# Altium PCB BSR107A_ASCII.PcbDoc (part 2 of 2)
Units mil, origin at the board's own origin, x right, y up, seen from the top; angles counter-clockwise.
Board outline 2500 x 2500 mil, 4 copper layers (Top Layer, Signal Layer 1, Signal Layer 2, Bottom Layer), stack 64.4 mil thick; 58 components, 15 nets, 89 pads, 265 vias.
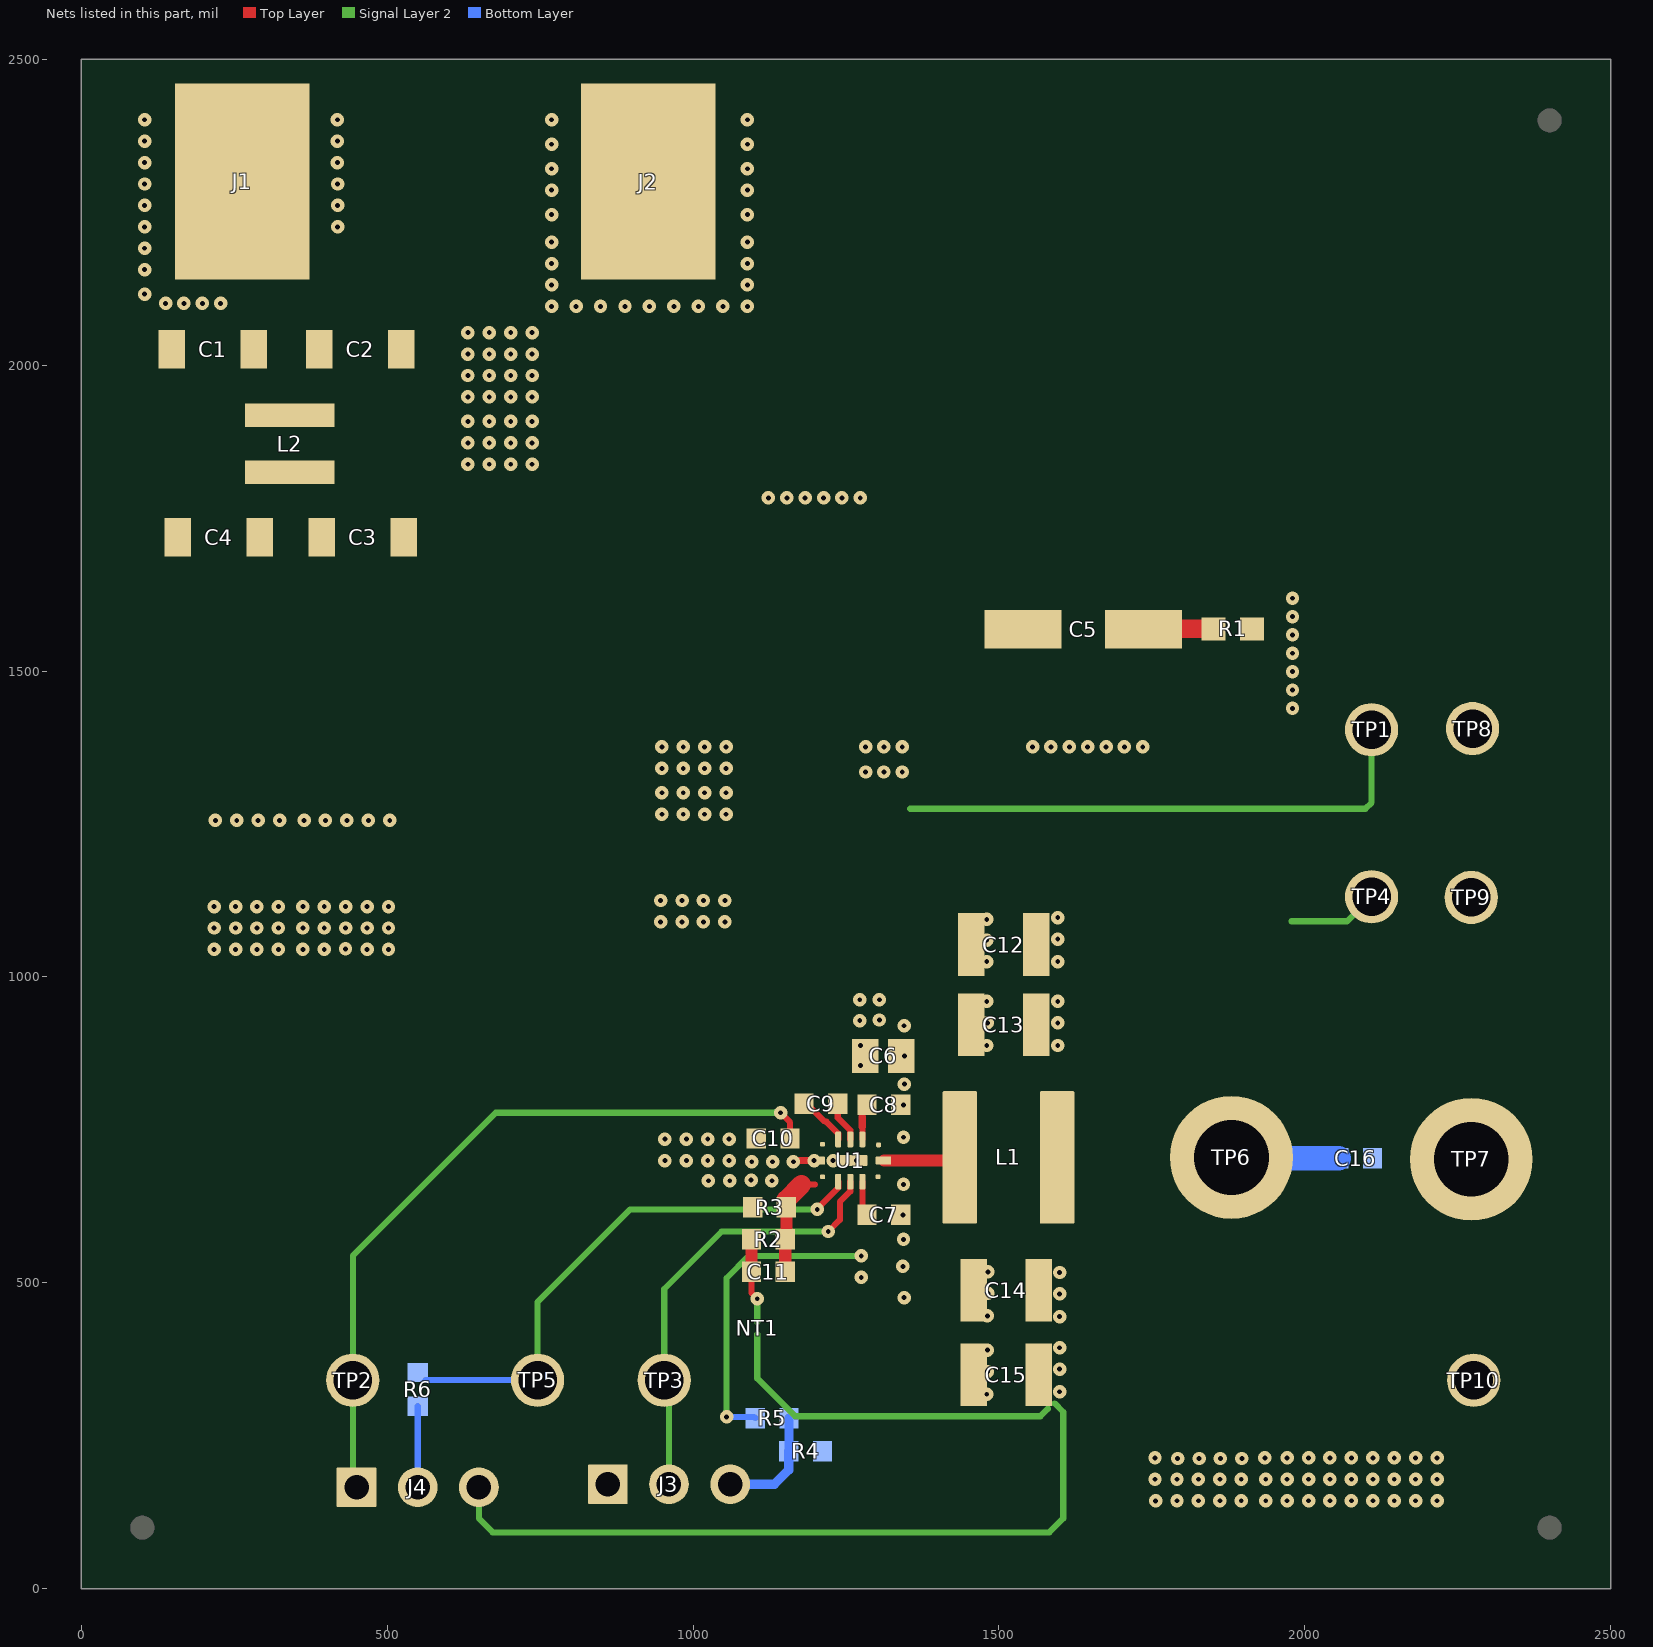
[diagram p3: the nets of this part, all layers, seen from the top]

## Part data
C1 C2 C3 C4: library part CMP-0008969-2, "CAP, CERM, 4.7 uF, 50 V, +/- 10%, X7R, 1206"
C5: library part CMP-0011179-2, "CAP, AL, 22 uF, 50 V, +/- 20%, 0.88 ohm, AEC-Q200 Grade 2, SMD"
C6: library part CMP-0007840-2, "CAP, CERM, 4.7 uF, 50 V, +/- 10%, X5R, 0805"
C7 C8: library part CMP-0007047-4, "CAP, CERM, 0.22 uF, 50 V, +/- 10%, X7R, 0603"
C9 C16: library part CMP-0006753-4, "CAP, CERM, 0.1 uF, 25 V, +/- 10%, X7R, 0603"
C10: library part CMP-0006833-4, "CAP, CERM, 1 uF, 25 V, +/- 10%, X7R, 0603"
C11: library part CMP-0007196-2, "CAP, CERM, 22 pF, 50 V, +/- 5%, C0G/NP0, 0603"
C12 C15: library part CMP-0009169-2, "CAP, CERM, 22 uF, 25 V, +/- 10%, X5R, 1210"
C13 C14: library part CMP-0009211-2, "CAP, CERM, 47 uF, 16 V, +/- 10%, X5R, 1210"
FID1 FID2 FID3 FID4 FID5 FID6: library part CMP-0077181-1, "Fiducial mark.  There is nothing to buy or mount."
J1: library part CMP-0055167-2, "Standard Banana Jack, Insulated, Red"
J2: library part CMP-0055168-2, "Standard Banana Jack, Insulated, Black"
J3 J4: library part CMP-0075484-1, "Header, 100mil, 3x1, Gold, TH"
L1: library part CMP-0061022-2, "Inductor, Shielded, Composite, 6.8 µH, 9 A, 0.0208 ohm, AEC-Q200 Grade 1, SMD"
L2: library part CMP-0060989-1, "Inductor, Shielded, Composite, 3.3 uH, 5.5 A, 0.026 ohm, SMD"
Logo1: library part CMP-0074838-1, "Texas Instrument Corporate Signature"
Logo2: library part CMP-0074844-1
Logo3: library part CMP-0074847-1, "FCC_disclaimer"
Logo4: library part CMP-0074769-1
LOGO5: library part CMP-0074837-1, "IEC 61010-1 Hot Surface Warning"
NT1: library part CMP-0078142-2, "Single point connection between nets."
R1: library part CMP-0023343-3, "RES, 0, 1%, 0.1 W, AEC-Q200 Grade 0, 0603"
R2: library part CMP-0022735-5, "RES, 100 k, 1%, 0.1 W, 0603"
R3: library part CMP-0022237-4, "RES, 24.9 k, 1%, 0.1 W, AEC-Q200 Grade 0, 0603"
R4 R5: library part CMP-0021998-4, "RES, 10.0 k, 1%, 0.1 W, AEC-Q200 Grade 0, 0603"
R6: library part CMP-0021990-4, "RES, 100 k, 1%, 0.1 W, AEC-Q200 Grade 0, 0603"
SH-J1 SH-J2: library part CMP-0003623-1, "Shunt, 100mil, Gold plated, Black"
TP1 TP4: library part CMP-0055147-1, "Test Point, Multipurpose, Red, TH"
TP2 TP3 TP5: library part CMP-0055151-1, "Test Point, Multipurpose, Yellow, TH"
TP6 TP7: library part 1503-2, "Terminal, Turret, TH, Double"
TP8 TP9 TP10: library part CMP-0055148-1, "Test Point, Multipurpose, Black, TH"
U1: library part CMP-0085873-1, "LM60440-Q1, RPK0013A (VQFN-12)"
ZZ2: library part CMP-0077236-1
ZZ3: library part CMP-0077237-1
ZZ4: library part CMP-0077238-1
ZZ5 ZZ6: library part CMP-0077238-1, "These assemblies must comply with workmanship standards IPC-A-610 Class 2, unless otherwise specified."

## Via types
v1: diameter 22, hole 8, Top Layer to Bottom Layer, 252 vias
v2: diameter 22, hole 8, Top Layer to Bottom Layer, tented both sides, 13 vias

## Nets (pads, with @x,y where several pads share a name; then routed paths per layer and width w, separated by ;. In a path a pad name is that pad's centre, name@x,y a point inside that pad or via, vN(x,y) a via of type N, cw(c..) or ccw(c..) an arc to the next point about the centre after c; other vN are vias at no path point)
BOOT: C9.2 U1.4 | length 91.7
  Top Layer w10: C9.2@1181.44,793 C9.2@1185.98,793 ; C9.2@1191.02,790.71 1188.73,793 C9.2@1185.98,793 ; U1.4@1237.31,734.45 1237.31,743.94 1217.78,763.47 1215.51,763.47 C9.2@1185.98,793
EN: J3.2 TP3.1 U1.9 | length 736.5
  Top Layer w10: v1(1221,584) 1240,603 1240,632.58 1257,649.58 U1.9@1257,665.55
  Signal Layer 2 w10: J3.2@960.67,170.89 960.67,333.33 TP3.1@953,341 953,490 1047,584 v1(1221,584)
  Bottom Layer w10: J3.2@953,178.56 J3.2@960.67,170.89
FB: C11.2 R2.1 R3.2 U1.7 | length 174.9
  Top Layer w10: R2.1@1151.56,571 R2.1@1152.56,572 ; R3.2@1152.56,624 R3.2@1152.56,635.81 ; 1177.38,660.63 1199,660.63
  Top Layer w20: C11.2@1150.56,518 R2.1@1150.56,571 ; R2.1@1152.56,572 R3.2@1152.56,624
  Top Layer w31.5: R3.2@1152.56,635.81 1177.38,660.63
GND: C1.2 C2.2 C3.2 C4.2 C6.2 C7.2 C8.2 C10.2 C12.2 C13.2 C14.2 C15.2 C16.2 J2.1 J3.1 R1.1 R3.1 R4.1 TP7.1 TP8.1 TP9.1 TP10.1 U1.1 U1.6 U1.11 U1.13 | length 58
  Top Layer w10: C3.2@526.93,1719 C3.2@527.93,1720 ; U1.13@1257,700 U1.13@1276.69,700
  Top Layer w12: v1@1166,700 U1.6@1202.87,700
  other v1: 1756,143.73 1791,144 1826,144 1861,144 1896,144 1936,144 1971,144 2006,144 2041,144 2076,144 2111,144 2146,144 2181,144 2216,144 1755,179 1791,179 1826,179 1861,179 1896,179 1936,179 1971,179 2006,179 2041,179 2076,179 2111,179 2146,179 2181,179 2216,179 1792,213 1827,213 1862,213 1897,213 1755,214 1934.73,214 1971,214 2006,214 2041,214 2076,214 2111,214 2146,214 2181,214 2216,214 1345,476 1343,527 1344,571 1343.43,611 1344,661 1025,667 1060,667 1129,667 1095,668 1096,698 1130,698 1164,698 954,700 989,700 1024,700 1059,700 1197.95,699.99 1229,700 1266.84,700 954,735 989,735 1024,735 1059,735 1344,738 1344,791 1345.45,871 1345,920.19 217.27,1045 252.27,1045 287.27,1045 322.27,1045 362.27,1045 397.27,1045 467.27,1045 502.27,1045 432,1046 217.27,1080 252.27,1080 287.27,1080 322.27,1080 362.27,1080 397.27,1080 432.27,1080 467.27,1080 502.27,1080 947,1090 982,1090 1017,1090 1052,1090 217.27,1115 252.27,1115 287.27,1115 322.27,1115 362.27,1115 397.27,1115 432.27,1115 467.27,1115 502.27,1115 947,1125 982,1125 1017,1125 1052,1125 219.27,1256 254.27,1256 289.27,1256 324.27,1256 364.27,1256 399.27,1256 434.27,1256 469.27,1256 504.27,1256 949,1266 984,1266 1019,1266 1054,1266 949,1301 984,1301 1019,1301 1054,1301 949,1341 984,1341 1019,1341 1054,1341 949,1376 984,1376 1019,1376 1054,1376 1555,1376 1585,1376 1615,1376 1645,1376 1675,1376 1705,1376 1735,1376 1979.72,1439 1979.72,1469 1979.72,1499 1979.72,1529 1979.72,1559 1979.72,1589 1979.72,1619 1123.27,1783 1153.27,1783 1183.27,1783 1213.27,1783 1243.27,1783 1273.27,1783 632,1838 667,1838 702,1838 737,1838 632,1873 667,1873 702,1873 737,1873 632,1908 667,1908 702,1908 737,1908 632,1948 667,1948 702,1948 737,1948 632,1983 667,1983 702,1983 737,1983 632,2018 667,2018 702,2018 737,2018 632,2053 667,2053 702,2053 737,2053 768.77,2096 808.77,2096 848.77,2096 888.77,2096 928.77,2096 968.77,2096 1008.77,2096 1048.77,2096 1088.77,2096 138,2101 168,2101 198,2101 228,2101 103.77,2116 768.77,2131 1088.77,2131 103.77,2156 768.77,2166 1088.77,2166 103.77,2191 768.77,2201 1088.77,2201 103.77,2226 419,2226 768.77,2246 1088.77,2246 103.77,2261 419,2261 768.77,2286 1088.77,2286 103.77,2296 419,2296 768.77,2321 1088.77,2321 103.77,2331 418.77,2331 768.77,2361 1088.77,2361 103.77,2366 418.77,2366 103.77,2401 418.77,2401 768.77,2401 1088.77,2401
  other v2: 1480,318 1481,355 1481,390 1481,446 1482,483 1482,518 1345.45,825 1480,888 1481,925 1480,960 1480,1025 1480,1060 1480,1094
NetC5_2: C5.2 R1.2 | length 96.1
  Top Layer w10: C5.2@1736.43,1568 C5.2@1737.43,1569
  Top Layer w30: C5.2@1737.43,1569 1810.44,1569 R1.2@1832.13,1569
NetJ4_2: J4.2 R6.1 | length 150.8
  Bottom Layer w10: R6.1@550,298.44 J4.2@550,166 J4.2@563,179
PGOOD: R6.2 TP5.1 U1.8 | length 890.3
  Top Layer w10: v1(1203,620) 1203,621.17 1237.31,655.48 U1.8@1237.31,665.55
  Signal Layer 2 w10: TP5.1@746,341 746,469 897,620 v1(1203,620)
  Bottom Layer w10: R6.2@563,341 TP5.1@746,341
SW1: L1.1 U1.12 | length 127.9
  Top Layer w20: U1.12@1312.13,700 L1.1@1440,700
SW2: C9.1 U1.3 | length 72.1
  Top Layer w10: C9.1@1227.7,793 C9.1@1230.64,788.83 ; C9.1@1236.56,793 1236.56,769.86 1257,749.42 U1.3@1257,734.45
VCC: C10.1 J4.1 TP2.1 U1.5 | length 1224
  Top Layer w10: v1(1143,778) 1158.56,762.44 C10.1@1158.56,736
  Signal Layer 2 w10: J4.1@444,166 TP2.1@444,341 444,544.43 677.57,778 v1(1143,778) v1@1144,777
VDIV: J3.3 R4.2 R5.1 | length 190.3
  Bottom Layer w10: R4.2@1156.44,225 R4.2@1156.91,225.46
  Bottom Layer w15: J3.3@1060.67,170.89 1132.89,170.89 1156.44,194.44 R4.2@1156.44,225 ; R4.2@1156.91,225.46 R5.1@1156.91,279
VIN: C1.1 C2.1 J1.1 L2.1 | length 75
  Top Layer w20: J1.1@263.77,2309 J1.1@316.77,2256
VINS: C3.1 C4.1 C5.1 C6.1 C7.1 C8.1 L2.2 R5.2 TP1.1 U1.2 U1.10 | length 1492.4
  Top Layer w10: U1.10@1276.68,665.55 1276.68,618.76 C7.1@1284.44,611 ; U1.2@1276.68,734.45 1276.68,755.27 ; C8.1@1276.68,783.24 C8.1@1284.44,791
  Top Layer w12: 1276.68,755.27 1276.68,771.43
  Signal Layer 2 w10: v1(1055,281) 1055,508 1091,544 v1(1275,544) ; 1355,1275 2099,1275 2109,1285 TP1.1@2109,1404
  Bottom Layer w10: v1(1055,281) 1099.79,281 R5.2@1101.79,279
  other v1: 1275,509 1274,855 1274,888 1272.44,928.68 1304.44,929.68 1272.44,962.68 1304.44,962.68 1282,1335 1312,1335 1342,1335 1282,1376 1312,1376 1342,1376
VOS: C11.1 NT1.1 R2.2 | length 141
  Top Layer w10: R2.2@1094,569.56 R2.2@1095.44,571 ; C11.1@1095.44,518 1095.44,483.56 v1(1105,474)
  Top Layer w20: C11.1@1095.44,518 R2.2@1095.44,571
  Signal Layer 2 w10: NT1.1@1105,436 v1(1105,474)
VOUT: C12.1 C13.1 C14.1 C15.1 C16.1 J4.3 L1.2 NT1.2 TP4.1 TP6.1 | length 2118.5
  Signal Layer 2 w10: J4.3@650,166 650,115 672.71,92.29 1582.29,92.29 1605,115 1605,289 1591,303 ; NT1.2@1105,416 1105,343.83 1166.83,282 1567.8,282 1580,294.2 ; 1978,1091 2069,1091 TP4.1@2109,1131
  Bottom Layer w40: TP6.1@1881,704 C16.1@2055.44,704
  other v1: 1599,322 1599,359 1599,394 1599,445 1599,482 1599,517 1596,888 1596,925 1596,960 1596,1025 1596,1062 1596,1097
pads on no net: FID1.1 FID2.1 FID3.1 FID4.1 FID5.1 FID6.1 SH-J1.0 SH-J2.0

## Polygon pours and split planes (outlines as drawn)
GND on Top Layer "TOP_LAYER_GND_P106" (solid, pour order 106): 23,2482 24,2483 2500,2483 2500,16 17,16 17,2479 21,2483
VINS on Top Layer "TOP_LAYER_VINS_P094" (solid, pour order 94): 360,1647.5 1602,1647.5 1602,1480 360,1480
VINS on Top Layer "TOP_LAYER_VINS_P044" (solid, remove dead copper, pour order 44): 422,1479 422,1844 265,1844 265,1479
VIN on Top Layer "TOP_LAYER_VIN_P010" (solid, remove dead copper, pour order 10): 258.77,2178.5 258.77,1896 423.77,1896 423.77,2178.5
VINS on Top Layer "TOP_LAYER_VINS_P084" (solid, pour order 84): 1318,980 1308,990 1254,990 1254,771.32 1318,771.32
SW1 on Top Layer "TOP_LAYER_SW1_P082" (solid, pour order 82): 1360,710.5 1409.43,812 1409.43,597 1360,690.5 1361,710.5
GND on Signal Layer 2 "SIGNAL_LAYER_2_GND_P097" (solid, pour order 97): 28,2479 2500,2479 2500,25.49 29.04,25.49 28,26.53
VINS on Signal Layer 2 "SIGNAL_LAYER_2_VINS_P095" (solid, pour order 95): 1243,1388 1224,1388 1316,1388 1316,1296.78 1323,1289.78 1323,395 1243,395 1243,1353.27 1243,1374
GND on Signal Layer 1 "SIGNAL_LAYER_1_GND_P096" (solid, pour order 96): 28,2479 2500,2479 2500,25.49 25.49,25.49 28,28
GND on Bottom Layer "BOTTOM_LAYER_GND_P098" (solid, pour order 98): 28,2479 2420,2479 2500,2479 2500,25.49 25.49,25.49 25.49,2484.51

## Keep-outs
Keep-Out Layer:
  text ".Layer_Name" at 444.27,-1053.49 h60

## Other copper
Top Layer:
  rectangle net FB: 1170.24,653 1215.81,680
  rectangle net VCC: 1145,721 1211.72,747
  rectangle net VINS: 1254,1307 1367,1585
  rectangle net VOUT: 1507,287 1628,1113.15
  rectangle net VINS: 1258,492.41 1311,630
  rectangle net VINS: 1273.44,914.68 1304.44,980.68
  text ".Layer_Name" at 444.27,-1053.49 h60
Signal Layer 2:
  rectangle net VINS: 1242,1255 1385,1402
  rectangle net VOUT: 1565,264 1994,1114
Bottom Layer:
  text ".Layer_Name" at 444.27,-1053.49 h60

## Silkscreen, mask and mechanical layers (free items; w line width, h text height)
Top Overlay:
  lines w15: 1320.82,751.2 1321.02,751
  text "BSR107A" at 1527.64,2044 h60
  text "LM60440AQEVM" at 1525.46,1959 h60
  text "VCC" at 389,59 h60
  text "GND" at 797,59 h60
  text "VDIV" at 1014,58 h60
  text "VOUT" at 587,55 h60
  text ".Layer_Name" at 444.27,-1053.49 h60
Bottom Overlay:
  text ".Layer_Name" at 444.27,-1053.49 h60
Top Paste:
  text ".Layer_Name" at 444.27,-1053.49 h60
Bottom Paste:
  text ".Layer_Name" at 444.27,-1053.49 h60
Top Solder:
  text ".Layer_Name" at 444.27,-1053.49 h60
  text ".Layer_Name" at 444.27,-1053.49 h60
Bottom Solder:
  text ".Layer_Name" at 444.27,-1053.49 h60
Drill Guide:
  text ".Layer_Name" at 444.27,-1053.49 h60
M1 Board Outline:
  the board outline again, w10
  text ".Layer_Name" at 444.27,-1053.49 h60
M2 Board Dimensions:
  rectangle: -7.73,-595 367.27,-470
  rectangle: -132.73,-470 -7.73,-345
  lines w7: -132.73,-470 867.27,-470 ; -7.73,-595 -7.73,-345 ; 117.27,-595 117.27,-345 ; 367.27,-595 367.27,-345 ; 617.27,-595 617.27,-345 ; -132.73,-595 -132.73,-345 867.27,-345 867.27,-595 -132.73,-595
  text ".Layer_Name" at 444.27,-1053.49 h60
M3 3D STEP Top:
  text ".Layer_Name" at 444.27,-1053.49 h60
M4 3D STEP Bottom:
  text ".Layer_Name" at 444.27,-1053.49 h60
M5 Assembly Top:
  lines w10: -424.73,-1125.17 6175.27,-1125.17 ; -424.73,-921.83 6177.27,-921.83 ; -424.73,-718.5 -424.73,-1328.5 3580.27,-1328.5 6177.27,-1328.5 6177.27,-718.5 -424.23,-718.5 -424.23,-1328.5 1151.27,-1328.5 ; 2040.27,-1328.5 2040.27,-718.5 ; 4769.27,-1335 4769.27,-1132.17
  text "COMPONENTS MARKED 'DNP' SHOULD NOT BE POPULATED." at 1020.77,-513.5 h60
  text "ASSEMBLY VARIANT:" at 1020.27,-629 h60
  text ".VariantName" at 2056.27,-629 h60
  text "PCB VIEWED FROM TOP SIDE" at -361.23,-850.67 h60
  text "BOARD #:" at 2115.27,-850.67 h60
  text ".PRJ_Number" at 2660.77,-850.67 h60
  text "TID #:" at 2115.27,-1054 h60
  text ".TID" at 2660.77,-1054 h60
  text "PLOT NAME =" at -361.23,-1259.34 h60
  text ".plot_File_Name" at 444.27,-1259.34 h60
  text "GENERATED    :" at 2117.27,-1259.34 h60
  text ".Print_Date" at 2986.77,-1259.34 h60
  text ".Print_Time" at 3715.77,-1259.34 h60
  text "TEXAS INSTRUMENTS" at 4980.27,-1259.34 h60
M6 Assembly Bottom:
  lines w10: -425.23,-922.33 6176.77,-922.33 ; -423.23,-1125.67 6176.77,-1125.67 ; 982.77,-1335.5 982.77,-1132.67 ; 1604.77,-922.33 1604.77,-719 ; 2444.77,-922.33 2444.77,-719 ; 3711.77,-1329 3711.77,-719 ; 4600.77,-1329 6176.27,-1329 6176.27,-719 -425.23,-719 -425.23,-1329 2171.77,-1329 6176.77,-1329 6176.77,-719
  text "COMPONENTS MARKED 'DNP' SHOULD NOT BE POPULATED." at 5969.27,-513 h60
  text ".VersionControl_RevNumber" at 902.77,-851.17 h60
  text "SVN REV:" at 1408.77,-851.17 h60
  text ".PCB_Rev" at 1955.27,-851.17 h60
  text "REV:" at 2246.77,-851.17 h60
  text ".PRJ_Number" at 3091.27,-851.17 h60
  text "BOARD #:" at 3636.77,-851.17 h60
  text ".TID" at 3091.27,-1054.5 h60
  text "TID #:" at 3636.77,-1054.5 h60
  text "TEXAS INSTRUMENTS" at 771.77,-1259.84 h60
  text ".Print_Time" at 2036.27,-1259.84 h60
  text ".Print_Date" at 2765.27,-1259.84 h60
  text "GENERATED    :" at 3634.77,-1259.84 h60
  text ".plot_File_Name" at 5307.77,-1259.84 h60
  text "PLOT NAME =" at 6113.27,-1259.84 h60
M9 Title Sheet:
  lines w10: -624.23,846.5 -424.23,846.5 ; -624.23,3221.5 -424.23,3221.5 ; -624.23,5596.5 -424.23,5596.5 ; 1875.77,-1528.5 1875.77,-1328.5 ; 1875.77,7771.5 1875.77,7971.5 ; 4375.77,-1528.5 4375.77,-1328.5 ; 4375.77,7771.5 4375.77,7971.5 ; 6188.27,-1328.5 6188.27,-718.5 11170.77,-718.5 ; 6875.77,-1528.5 6875.77,-1328.5 ; 6875.77,7771.5 6875.77,7971.5 ; 9375.77,-1528.5 9375.77,-1328.5 ; 9375.77,7771.5 9375.77,7971.5 ; 11170.77,-1328.5 11170.77,-718.5 ; 11170.77,-1018.5 14170.77,-1018.5 ; 11170.77,-418.5 14170.77,-418.5 ; 11171.77,175.5 14171.77,175.5 ; 11875.77,-1528.5 11875.77,-1328.5 ; 11875.77,7771.5 11875.77,7971.5 ; 12675.77,-1318.5 12675.77,-718.5 ; 14170.77,-718.5 11170.77,-718.5 ; 14170.77,-118.5 11170.77,-118.5 ; 14175.77,-128.5 14175.77,-1328.5 ; 14175.77,676 11171.77,676 11170.77,676 11170.77,175.5 11170.77,-118.5 ; 14175.77,846.5 14375.77,846.5 ; 14175.77,3221.5 14375.77,3221.5 ; 14175.77,5596.5 14375.77,5596.5 ; 11170.77,-718.5 11170.77,-118.5 ; 14175.77,-1328.5 -424.23,-1328.5 -424.23,7771.5 14175.77,7771.5 14175.77,-1328.5 ; -624.23,-1528.5 14375.77,-1528.5 14375.77,7971.5 -624.23,7971.5 -624.23,-1528.5
  text "1" at 607.11,7841.5 h70
  text "2" at 3102.77,7841.5 h70
  text "3" at 5592.12,7841.5 h70
  text "4" at 8098.78,7841.5 h70
  text "5" at 10597.77,7841.5 h70
  text "6" at 13102.77,7841.5 h70
  text "A" at -549.23,6698.5 h70
  text "A" at 14250.77,6698.5 h70
  text "B" at -549.23,4318.5 h70
  text "B" at 14250.77,4318.5 h70
  text "C" at -549.23,1943.5 h70
  text "C" at 14250.77,1943.5 h70
  text "PROJECT TITLE:" at 11210.77,82.5 h45
  text ".PRJ_Title" at 11260.77,-50.83 h70
  text "DESIGNED FOR:" at 11210.77,-218.5 h45
  text ".PRJ_Customer" at 11260.77,-358.5 h70
  text "D" at -549.23,-426.5 h70
  text "D" at 14250.77,-426.5 h70
  text "FILE NAME:" at 11210.77,-518.5 h45
  text ".PCB_File_Name_No_Path" at 11260.77,-638.5 h70
  text "Texas Instruments (TI) and/or its licensors do not warrant the accuracy or completeness of this specification" at 6241.27,-800.34 h45
  text "ENGINEER:" at 11210.77,-808.5 h45
  text "LAYOUT BY:" at 12715.77,-808.5 h45
  text "or any information contained therein. TI and/or its licensors do not warrant that this design will meet" at 6196.29,-913 h45
  text ".PRJ_Engineer" at 11260.77,-963.49 h70
  text ".PCB_Layout" at 12766.27,-963.49 h70
  text "the specifications, will be suitable for your application or fit for any particular purpose, or will operate in" at 6196.29,-1025.67 h45
  text ".Layer_Name" at 444.27,-1053.49 h60
  text "ALTIUM DESIGNER VERSION:" at 12715.77,-1118.5 h45
  text "an implementation. TI and/or its licensors do not warrant that the design is production worthy. You should" at 6196.29,-1138.33 h45
  text "completely validate and test your design implementation to confirm the system functionality for your application." at 6241.27,-1251 h45
  text ".print_Scale" at 11260.77,-1251.83 h70
  text ".Application_BuildNumber" at 12766.27,-1251.83 h70
  text "1" at 607.11,-1458.5 h70
  text "2" at 3102.77,-1458.5 h70
  text "3" at 5592.12,-1458.5 h70
  text "4" at 8098.78,-1458.5 h70
  text "5" at 10597.77,-1458.5 h70
  text "6" at 13102.77,-1458.5 h70
M10 Fab Notes:
  drawing of 484 lines, arcs and shapes, not listed
  text "DESIGN INFORMATION" at 12249.29,6161.17 h60
  text "MIN. TRACK WIDTH:" at 11604.73,6029.05 h60
  text "8" at 12700.97,6029.05 h60
  text "MIL" at 12855.73,6029.05 h60
  text "7.795" at 12561,5912 h60
  text "MIN. CLEARANCE:" at 11604.73,5904.92 h60
  text "MIL" at 12855.73,5904.92 h60
  text "MIN. VIA PAD SIZE:" at 11604.73,5780.8 h60
  text "16" at 12670.98,5780.8 h60
  text "MIL" at 12855.73,5780.8 h60
  text "0.05mm (2MIL)" at 12299.73,5650.9 h60
  text "MINIMUM ANNULAR RING" at 11275.5,5642.67 h60
  text "EXTERNAL" at 13007.73,5642.67 h60
  text "PER" at 11475.5,5532.55 h60
  text "IPC-D-275 CLASS 2 LEVEL C" at 11695.5,5532.54 h60
  text "MIL, HOLES" at 13183.73,5432.07 h60
  text "+/-" at 12791.27,5423.48 h60
  text "+/-" at 13645.27,5423.48 h60
  text "REGISTRATION TOLERANCES:" at 11275.5,5422.42 h60
  text "METAL" at 12475.27,5422.42 h60
  text "5" at 13051.47,5422.42 h60
  text "3" at 13884.47,5422.42 h60
  text "MIL" at 14000.73,5422.42 h60
  text "HOLE SIZE TOLERANCE (UNLESS OTHERWISE SPECIFIED):" at 11275.5,5324.1 h60
  text "+/-" at 13645.27,5321.23 h60
  text "3" at 13884.47,5320.17 h60
  text "MIL" at 14000.73,5320.17 h60
  text "MATERIAL:" at 11200.73,5182.52 h60
  text "FR-4 High Tg" at 12187.18,5054 h60
  text "X" at 12042.74,5046.01 h60
  text "FR-408" at 11621.73,5041.49 h60
  text "OTHER" at 13109.73,5041.49 h60
  text "65.2 MIL (1.6mm) +/-10%" at 11941.83,4898.46 h60
  text "X" at 11821.74,4896.01 h60
  text "THICKNESS:" at 11275.5,4890.24 h60
  text "OTHER" at 13226.73,4890.24 h60
  text "TOLERANCE:" at 11275.5,4751.92 h60
  text "X" at 12123.74,4751.92 h60
  text "ANSI IPC-6012 TYPE 3 CLASS 2" at 12301.75,4751.92 h60
  text "OTHER +/-" at 12301.73,4607.73 h60
  text "BOW & TWIST:" at 11275.5,4462.54 h60
  text "X" at 12123.74,4462.54 h60
  text "ANSI IPC-6012 TYPE 3 CLASS 2" at 12301.75,4462.54 h60
  text "OTHER +/-" at 12301.73,4315.85 h60
  text "DRILLING:" at 11200.73,4185.23 h60
  text "NC_DRILL FILES" at 12961.73,4080.04 h60
  text "REFERENCE:" at 11275.5,4076.1 h60
  text "X" at 11932.74,4076.01 h60
  text "AS SHOWN" at 12110.73,4076.1 h60
  text "X" at 12833.74,4076.1 h60
  text "OTHER" at 13259.73,3933.85 h60
  text "PTH COPPER THICKNESS:" at 11275.18,3930.32 h60
  text "X" at 12414.41,3930.32 h60
  text "20-30 um" at 12542.41,3930.32 h60
  text "BOARD FINISH:" at 11200.73,3782.73 h60
  text "SILKSCREEN:" at 11355.95,3672.6 h60
  text "X" at 12313.74,3672.6 h60
  text "TOP" at 12430.73,3672.6 h60
  text "X" at 12823.74,3672.6 h60
  text "BOTTOM" at 12941.73,3672.6 h60
  text "SILKSCREEN COLOR:" at 11355.95,3517.41 h60
  text "X" at 12312.74,3517.41 h60
  text "WHITE" at 12430.73,3517.41 h60
  text "OTHER" at 12941.73,3517.41 h60
  text "X" at 12443.74,3373.96 h60
  text "GREEN" at 12561.73,3373.96 h60
  text "OTHER" at 13179.73,3373.96 h60
  text "SOLDER RESIST COLOR:" at 11355.95,3367.1 h60
  text "X" at 12443.74,3219.71 h60
  text "MATTE" at 12561.73,3219.71 h60
  text "SEMI-GLOSS" at 13179.27,3219.07 h60
  text "IMMERSION GOLD (ENIG)" at 12261.73,3046.94 h60
  text "ENEPIG" at 13599.27,3039.72 h60
  text "SURFACE FINISH:" at 11200.73,3038.72 h60
  text "X" at 12083.74,3038.72 h60
  text "IMM. TIN/SILVER OR EQUIV" at 11530.27,2901.4 h60
  text "OTHER" at 12961.73,2897.47 h60
  text "ARRAY/PANEL:" at 11200.73,2742.09 h60
  text "X" at 12080,2735 h60
  text "CUT AND TRIM PER M1 BOARD OUTLINE" at 12261.73,2733.87 h60
  text "N.C. ROUTE" at 12261.73,2597.9 h60
  text "V. SCORE" at 13127.73,2597.9 h60
  text "CERTIFICATION:" at 11200.73,2468.77 h60
  text "MATERIALS AND WORKMANSHIP FOR ALL PCBS" at 11925.73,2468.77 h60
  text "TO MEET OR EXCEED THE REQUIREMENTS OF:" at 11925.73,2374.71 h60
  text "Layer" at 3631.74,2339 h60
  text "Name" at 4041.66,2339 h60
  text "Material" at 4981.4,2339 h60
  text "Thickness" at 5841.16,2339 h60
  text "Constant" at 6491,2339 h60
  text "Board Layer Stack" at 7060.86,2339 h60
  text "X" at 11563.24,2246.08 h60
  text "ANSI IPC-A-600F CLASS ->" at 11691.24,2246.08 h60
  text "X" at 13339.24,2246.08 h60
  text "2" at 13449.24,2246.08 h60
  text "1" at 13134.24,2244.58 h60
  text "3" at 13803.24,2244.58 h60
  text "1" at 3631.74,2219 h60
  text "Top Overlay" at 4041.66,2219 h60
  text "2" at 3631.74,2099 h60
  text "Top Solder" at 4041.66,2099 h60
  text "Solder Resist" at 4981.4,2099 h60
  text "0.40mil" at 5841.16,2099 h60
  text "3.5" at 6491,2099 h60
  text "X" at 12375.24,2098.39 h60
  text "RoHS" at 12503.24,2098.39 h60
  text "OTHER" at 13147.64,2098.39 h60
  text "PER ORDER" at 13544.69,2098.39 h60
  text "3" at 3631.74,1979 h60
  text "Top Layer" at 4041.66,1979 h60
  text "Copper" at 4981.4,1979 h60
  text "2.80mil" at 5841.16,1979 h60
  text "ALL BOARDS MUST MEET OR EXCEED UL94-V0 REQUIREMENTS." at 11228.27,1944.57 h60
  text "4" at 3631.74,1859 h60
  text "Dielectric 3" at 4041.66,1859 h60
  text "FR-4 High TG" at 4981.4,1859 h60
  text "14.00mil" at 5841.16,1859 h60
  text "4.2" at 6491,1859 h60
  text "PCB MUST BEAR THE UL94V-0 UL REGISTERED MATERIAL ID NUMBER" at 11228.27,1828.5 h60
  text "5" at 3631.74,1739 h60
  text "Signal Layer 1" at 4041.66,1739 h60
  text "Copper" at 4981.4,1739 h60
  text "1.40mil" at 5841.16,1739 h60
  text "ADDITIONAL REQUIREMENTS:" at 11200.73,1659.08 h60
  text "6" at 3631.74,1619 h60
  text "Dielectric 2" at 4041.66,1619 h60
  text "FR-4 High TG" at 4981.4,1619 h60
  text "28.00mil" at 5841.16,1619 h60
  text "4.2" at 6491,1619 h60
  text "MICROSECTION:" at 11275.5,1551.95 h60
  text "YES" at 12181.24,1551.95 h60
  text "7" at 3631.74,1499 h60
  text "Signal Layer 2" at 4041.66,1499 h60
  text "Copper" at 4981.4,1499 h60
  text "1.40mil" at 5841.16,1499 h60
  text "REQUIRED" at 13042.73,1407.62 h60
  text "BARE BOARD ELEC. TEST:" at 11275.5,1404.76 h60
  text "NONE" at 12581.24,1404.76 h60
  text "X" at 12924.74,1404.76 h60
  text "PER ORDER" at 13634.73,1404.76 h60
  text "8" at 3631.74,1379 h60
  text "Dielectric1" at 4041.66,1379 h60
  text "FR-4 HIgh TG" at 4981.4,1379 h60
  text "14.00mil" at 5841.16,1379 h60
  text "4.2" at 6491,1379 h60
  text "9" at 3631.74,1259 h60
  text "Bottom Layer" at 4041.66,1259 h60
  text "Copper" at 4981.4,1259 h60
  text "2.80mil" at 5841.16,1259 h60
  text "XX MIL VIAS REQUIRE NON-CONDUCTIVE FILL AND PLANARIZE" at 11443.65,1199.82 h59
  text "10" at 3631.74,1139 h60
  text "Bottom Solder" at 4041.66,1139 h60
  text "Solder Resist" at 4981.4,1139 h60
  text "0.40mil" at 5841.16,1139 h60
  text "3.5" at 6491,1139 h60
  text "XX MIL VIAS REQUIRE CONDUCTIVE FILL AND PLANARIZE" at 11451.65,1095.84 h60
  text "11" at 3631.74,1019 h60
  text "Bottom Overlay" at 4041.66,1019 h60
  text "OUTER XX MIL VIAS REQUIRE 50 OHM SINGLE-ENDED IMPEDANCE" at 11450.67,932.46 h58
  text "LAYER 2 & 3 (INNER LAYERS) XX MIL WIDE, XX MIL SPACE / TRACES REQUIRE 100 OHM DIFFERENTIAL IMPEDANCE" at 11442.67,696.74 h60
  text ".Layer_Name" at 444.27,-1053.49 h60
M11 Gerber Information:
  lines w10: -424.73,-1125.17 6175.27,-1125.17 ; -424.73,-921.83 6177.27,-921.83 ; -424.73,-718.5 -424.73,-1328.5 3580.27,-1328.5 6177.27,-1328.5 6177.27,-718.5 -424.23,-718.5 -424.23,-1328.5 1151.27,-1328.5 ; 2040.27,-1328.5 2040.27,-718.5 ; 4769.27,-1335 4769.27,-1132.17
  text "ALL ARTWORK VIEWED FROM TOP SIDE" at -361.23,-850.67 h60
  text "BOARD #:" at 2115.27,-850.67 h60
  text ".PRJ_Number" at 2660.77,-850.67 h60
  text "LAYER NAME =" at -361.23,-1053.49 h60
  text "TID #:" at 2115.27,-1054 h60
  text ".TID" at 2660.77,-1054 h60
  text "PLOT NAME =" at -361.23,-1259.34 h60
  text ".plot_File_Name" at 444.27,-1259.34 h60
  text "GENERATED    :" at 2117.27,-1259.34 h60
  text ".Print_Date" at 2986.77,-1259.34 h60
  text ".Print_Time" at 3715.77,-1259.34 h60
  text "TEXAS INSTRUMENTS" at 4980.27,-1259.34 h60
M12 Stackup:
  text ".Layer_Name" at 444.27,-1053.49 h60
M13 Component Bodies Top:
  text ".Layer_Name" at 444.27,-1053.49 h60
M14 Component Bodies Bottom:
  text ".Layer_Name" at 444.27,-1053.49 h60
M15 Courtyards Top:
  text ".Layer_Name" at 444.27,-1053.49 h60
M16 Courtyards Bottom:
  text ".Layer_Name" at 444.27,-1053.49 h60
Drill Drawing:
  circle w10: c5230.99,3042.96 r27.63
  lines w10: 5203.36,2780.51 5217.18,2780.51 5230.99,2766.7 5244.8,2780.51 5258.62,2780.51 5244.8,2794.32 5258.62,2808.14 5244.8,2808.14 5230.99,2821.95 5217.18,2808.14 5203.36,2808.14 5217.18,2794.32 5203.36,2780.51 ; 5203.36,2891.02 5258.62,2891.02 5258.62,2946.27 5203.36,2946.27 5203.36,2891.02 ; 5203.36,3139.66 5230.99,3153.47 5258.62,3139.66 5244.8,3167.28 5258.62,3194.91 5230.99,3181.1 5203.36,3194.91 5217.18,3167.28 5203.36,3139.66
  lines w12: 5153.27,2729.4 8384.76,2729.4 ; 5153.27,3226.68 8384.76,3226.68 ; 5491.13,2605.08 5491.13,3351 ; 5823.14,2605.08 5823.14,3351 ; 6459.7,2605.08 6459.7,3351 ; 6718.84,2605.08 6718.84,3351 ; 7094,2605.08 7094,3351 ; 7818.33,2605.08 7818.33,3351 ; 5153.27,2605.08 8384.76,2605.08 8384.76,3351 5153.27,3351 5153.27,2605.08
  text "Symbol" at 5227.86,3263.98 h72
  text "Quantity" at 5528.43,3263.98 h72
  text "Finished Hole Size" at 5860.43,3263.98 h72
  text "Plated" at 6496.99,3263.98 h72
  text "Hole Type" at 6756.13,3263.98 h72
  text "Drill Layer Pair" at 7131.29,3263.98 h72
  text "Hole Tolerance" at 7855.62,3263.98 h72
  text "265" at 5528.43,3139.66 h60
  text "8.00mil (0.203mm)" at 5860.43,3139.66 h60
  text "PTH" at 6496.99,3139.66 h60
  text "Round" at 6756.13,3139.66 h60
  text "Top Layer - Bottom Layer" at 7131.29,3139.66 h60
  text "6" at 5528.43,3015.34 h60
  text "40.00mil (1.016mm)" at 5860.43,3015.34 h60
  text "PTH" at 6496.99,3015.34 h60
  text "Round" at 6756.13,3015.34 h60
  text "Top Layer - Bottom Layer" at 7131.29,3015.34 h60
  text "8" at 5528.43,2891.02 h60
  text "63.00mil (1.600mm)" at 5860.43,2891.02 h60
  text "PTH" at 6496.99,2891.02 h60
  text "Round" at 6756.13,2891.02 h60
  text "Top Layer - Bottom Layer" at 7131.29,2891.02 h60
  text "2" at 5528.43,2766.7 h60
  text "122.05mil (3.100mm)" at 5860.43,2766.7 h60
  text "PTH" at 6496.99,2766.7 h60
  text "Round" at 6756.13,2766.7 h60
  text "Top Layer - Bottom Layer" at 7131.29,2766.7 h60
  text "281 Total" at 5528.43,2642.38 h60
  text ".Layer_Name" at 444.27,-1053.49 h60
M17 Embedded Cavity:
  text ".Layer_Name" at 444.27,-1053.49 h60
M18 Embedded Assembly:
  text ".Layer_Name" at 444.27,-1053.49 h60
M19 Embedded Keepout:
  text ".Layer_Name" at 444.27,-1053.49 h60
